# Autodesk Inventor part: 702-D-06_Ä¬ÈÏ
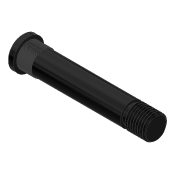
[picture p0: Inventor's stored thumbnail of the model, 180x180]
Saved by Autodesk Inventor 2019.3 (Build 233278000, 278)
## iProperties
Created: 2010-06
Part Number: 702-D-06_Ä¬ÈÏ
Material: Ogólny
Document SubType Name: Modeling
Designer: CADENGINEERING4
Density: 1 g/cm^3
Appearance: Gładki — czarny
Author: CADENGINEERING4
Revision Number: ÈÎºÎ
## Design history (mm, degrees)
feature "NONE"
node "Bryła1"
